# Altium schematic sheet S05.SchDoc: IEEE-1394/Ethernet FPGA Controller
size 381 x 254 mm; Revision: 3.2; SheetNumber: 5; SheetTotal: 10
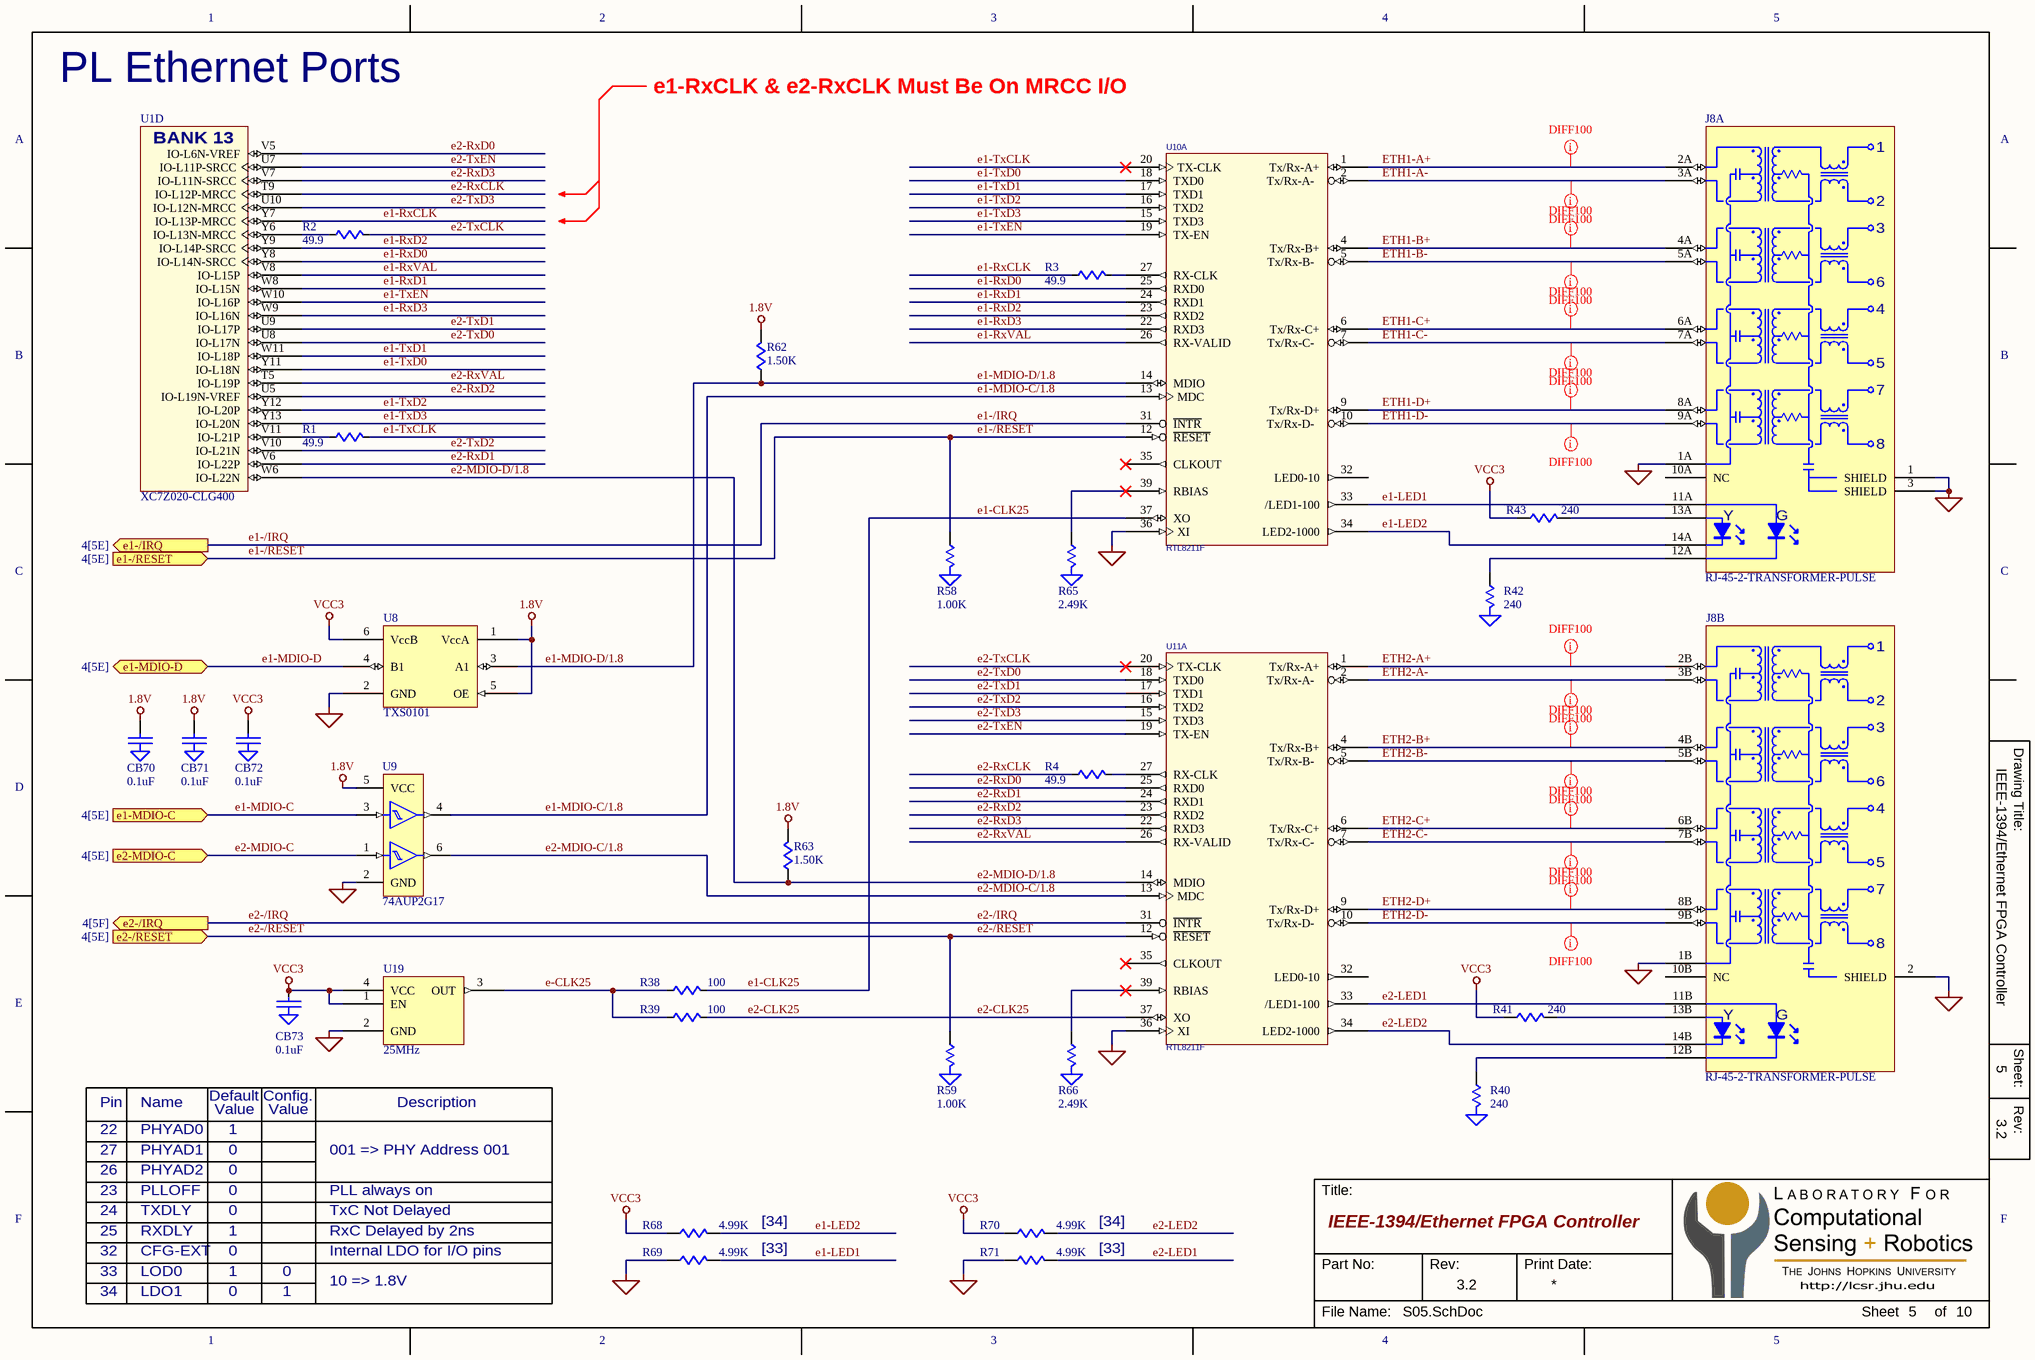
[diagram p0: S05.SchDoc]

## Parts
CB70  0.1uF  [C0201]
CB71  0.1uF  [C0201]
CB72  0.1uF  [C0201]
CB73  0.1uF  [C0201]
J8  RJ-45-2-TRANSFORMER-PULSE  [CONN-RJ-45-DUAL-PULSE-JXD0-2015NL]  (parts A,B of 2)
R1  49.9  [R0201]
R2  49.9  [R0201]
R3  49.9  [R0201]
R4  49.9  [R0201]
R38  100  [R0402]
R39  100  [R0402]
R40  240  [R0402]
R41  240  [R0402]
R42  240  [R0402]
R43  240  [R0402]
R58  1.00K  [R0402]
R59  1.00K  [R0402]
R62  1.50K  [R0402]
R63  1.50K  [R0402]
R65  2.49K  [R0402]
R66  2.49K  [R0402]
R68  4.99K  [R0402]
R69  4.99K  [R0402]
R70  4.99K  [R0402]
R71  4.99K  [R0402]
U1  XC7Z020-CLG400  [BGA-400-08mm]  (part D of 9)
U8  TXS0101  [SC70-6]
U9  74AUP2G17  [SC70-6]
U10  RTL8211F  [QFN-40-5MM]  (part A of 2)
U11  RTL8211F  [QFN-40-5MM]  (part A of 2)
U19  25MHz  [OSC-2x2.5mm]

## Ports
e1-/IRQ (out, see 4[5E]), e1-/RESET (in, see 4[5E]), e1-MDIO-C (in, see 4[5E]), e1-MDIO-D (bidir, see 4[5E]), e2-/IRQ (out, see 4[5F]), e2-/RESET (in, see 4[5E]), e2-MDIO-C (in, see 4[5E])

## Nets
1.8V: CB70.1 CB71.1 R62.2 R63.2 U8.1(VccA) U8.5(OE) U9.5(VCC)
GND: CB70.2(GND) CB71.2(GND) CB72.2(GND) CB73.2(GND) J8.1(SHIELD) J8.1A(GND) J8.1B(GND) J8.2(SHIELD) J8.3(SHIELD) R40.2(GND) R42.2(GND) R58.2(GND) R59.2(GND) R65.2(GND) R66.2(GND) R69.1 R71.1 U8.2(GND) U9.2(GND) U10.36(XI) U11.36(XI) U19.2(GND)
VCC3: CB72.1 CB73.1 R41.1 R43.1 R68.1 R70.1 U8.6(VccB) U19.1(EN) U19.4(VCC)
e1-/IRQ: U10.31(~{INTR}) ; port e1-/IRQ
e1-/RESET: R58.1 U10.12(~{RESET}) ; port e1-/RESET
e1-CLK25: R38.2 U10.37(XO)
e1-LED1: J8.11A(A(G)) R69.2 U10.33(/LED1-100)
e1-LED2: J8.14A(K(Y)) R68.2 U10.34(LED2-1000)
e1-MDIO-C: U9.3 ; port e1-MDIO-C
e1-MDIO-C/1.8: U9.4 U10.13(MDC)
e1-MDIO-D: U8.4(B1) ; port e1-MDIO-D
e1-MDIO-D/1.8: R62.1 U8.3(A1) U10.14(MDIO)
e1-RxCLK: R3.1 U1.Y7(IO-L13P-MRCC)
e1-RxD0: U1.Y8(IO-L14N-SRCC) U10.25(RXD0)
e1-RxD1: U1.W8(IO-L15N) U10.24(RXD1)
e1-RxD2: U1.Y9(IO-L14P-SRCC) U10.23(RXD2)
e1-RxD3: U1.W9(IO-L16N) U10.22(RXD3)
e1-RxVAL: U1.V8(IO-L15P) U10.26(RX-VALID)
e1-TxCLK: R1.2 U10.20(TX-CLK)
e1-TxD0: U1.Y11(IO-L18N) U10.18(TXD0)
e1-TxD1: U1.W11(IO-L18P) U10.17(TXD1)
e1-TxD2: U1.Y12(IO-L20P) U10.16(TXD2)
e1-TxD3: U1.Y13(IO-L20N) U10.15(TXD3)
e1-TxEN: U1.W10(IO-L16P) U10.19(TX-EN)
e2-/IRQ: U11.31(~{INTR}) ; port e2-/IRQ
e2-/RESET: R59.1 U11.12(~{RESET}) ; port e2-/RESET
e2-CLK25: R39.2 U11.37(XO)
e2-LED1: J8.11B(A(G)) R71.2 U11.33(/LED1-100)
e2-LED2: J8.14B(K(Y)) R70.2 U11.34(LED2-1000)
e2-MDIO-C: U9.1 ; port e2-MDIO-C
e2-MDIO-C/1.8: U9.6 U11.13(MDC)
e2-MDIO-D/1.8: R63.1 U1.W6(IO-L22N) U11.14(MDIO)
e2-RxCLK: R4.1 U1.T9(IO-L12P-MRCC)
e2-RxD0: U1.V5(IO-L6N-VREF) U11.25(RXD0)
e2-RxD1: U1.V6(IO-L22P) U11.24(RXD1)
e2-RxD2: U1.U5(IO-L19N-VREF) U11.23(RXD2)
e2-RxD3: U1.V7(IO-L11N-SRCC) U11.22(RXD3)
e2-RxVAL: U1.T5(IO-L19P) U11.26(RX-VALID)
e2-TxCLK: R2.2 U11.20(TX-CLK)
e2-TxD0: U1.U8(IO-L17N) U11.18(TXD0)
e2-TxD1: U1.U9(IO-L17P) U11.17(TXD1)
e2-TxD2: U1.V10(IO-L21N) U11.16(TXD2)
e2-TxD3: U1.U10(IO-L12N-MRCC) U11.15(TXD3)
e2-TxEN: U1.U7(IO-L11P-SRCC) U11.19(TX-EN)
e-CLK25: R38.1 R39.1 U19.3(OUT)
ETH1-A+: J8.2A(1P) U10.1(Tx/Rx-A+)
ETH1-A-: J8.3A(1N) U10.2(Tx/Rx-A-)
ETH1-B+: J8.4A(2P) U10.4(Tx/Rx-B+)
ETH1-B-: J8.5A(2N) U10.5(Tx/Rx-B-)
ETH1-C+: J8.6A(3P) U10.6(Tx/Rx-C+)
ETH1-C-: J8.7A(3N) U10.7(Tx/Rx-C-)
ETH1-D+: J8.8A(4P) U10.9(Tx/Rx-D+)
ETH1-D-: J8.9A(4N) U10.10(Tx/Rx-D-)
ETH2-A+: J8.2B(1P) U11.1(Tx/Rx-A+)
ETH2-A-: J8.3B(1N) U11.2(Tx/Rx-A-)
ETH2-B+: J8.4B(2P) U11.4(Tx/Rx-B+)
ETH2-B-: J8.5B(2N) U11.5(Tx/Rx-B-)
ETH2-C+: J8.6B(3P) U11.6(Tx/Rx-C+)
ETH2-C-: J8.7B(3N) U11.7(Tx/Rx-C-)
ETH2-D+: J8.8B(4P) U11.9(Tx/Rx-D+)
ETH2-D-: J8.9B(4N) U11.10(Tx/Rx-D-)
NetJ8_12A: J8.12A(K(G)) R42.1
NetJ8_12B: J8.12B(K(G)) R40.1
NetJ8_13A: J8.13A(A(Y)) R43.2
NetJ8_13B: J8.13B(A(Y)) R41.2
NetR1_1: R1.1 U1.V11(IO-L21P)
NetR2_1: R2.1 U1.Y6(IO-L13N-MRCC)
NetR3_2: R3.2 U10.27(RX-CLK)
NetR4_2: R4.2 U11.27(RX-CLK)
NetR65_1: R65.1 U10.39(RBIAS)
NetR66_1: R66.1 U11.39(RBIAS)

Not connected (* = marked no-connect by the designer): J8 10A(NC) 10B(NC); U10 32(LED0-10) 35(CLKOUT)*; U11 32(LED0-10) 35(CLKOUT)*

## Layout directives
net class DIFF100: ETH1-A+, ETH1-A-, ETH1-B+, ETH1-B-, ETH1-C+, ETH1-C-, ETH1-D+, ETH1-D-, ETH2-A+, ETH2-A-, ETH2-B+, ETH2-B-, ETH2-C+, ETH2-C-, ETH2-D+, ETH2-D-

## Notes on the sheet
- PL Ethernet Ports
- e1-RxCLK & e2-RxCLK Must Be On MRCC I/O
- Pin
- Name
- Default
- Value
- Config.
- Description
- 22
- 27
- 26
- PHYAD0
- PHYAD1
- PHYAD2
- 1
- 0
- 001 => PHY Address 001
- 23
- 24
- 25
- PLLOFF
- TXDLY
- RXDLY
- RxC Delayed by 2ns
- PLL always on
- TxC Not Delayed
- [34]
- 32
- 33
- 34
- LOD0
- LDO1
- CFG-EXT
- 10 => 1.8V
- Internal LDO for I/O pins
- [33]

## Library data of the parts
CB70-CB73 = CAP-GND
J8 = RJ-45-2-TRANSFORMER-PULSE: PULSE JXD0-2015NL
R1-R4 R38 R39 R41 R43 R62 R63 R68-R71 = R
R40 R42 R58 R59 R65 R66 = R-GND
U9 = 2G17-1: NC7WZ17
U10 U11 = RTL8211F: Ethernet PHY
U19 = OSCILATOR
